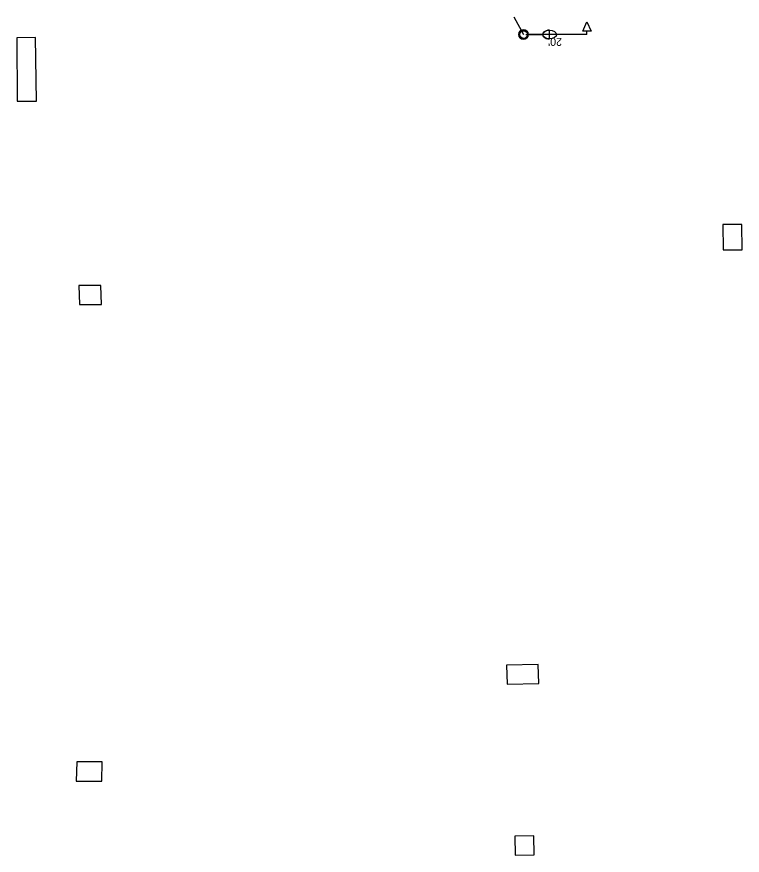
# Model space of a CAD drawing. Extents: x 596176 to 605330, y 332416 to 402398.
# Drawn here: x 601125.1 to 601353.5, y 385994.5 to 386258.5 of the extents above; entities that cross this region are included whole.
import ezdxf

# ---------------------------------------------------------------- set-up
doc = ezdxf.new("R2010")
doc.units = 0
for name, color, linetype in [('P_LTG', 7, 'Continuous'), ('P_SIG', 7, 'Continuous'), ('P_SIG_Conduit', 7, 'Continuous'), ('P_SIG_Loops', 7, 'Continuous')]:
    doc.layers.add(name, color=color, linetype=linetype)

# ---------------------------------------------------------------- blocks, each defined once
blk = doc.blocks.new('LUMINAIRES_3')
at = {"layer": 'P_LTG'}
for p, q in [((4.32, 25.12), (-4.14, 25.12)), ((0.05, 2.3), (0.05, 18.44))]:
    blk.add_line(p, q, dxfattribs=at)
blk.add_circle((0.05, 0.15), 3.68, dxfattribs=at)
blk.add_ellipse((0.09, 25.12), major_axis=(0, 6.65), ratio=0.636439, dxfattribs=at)
blk.add_ellipse((0.09, 25.12), major_axis=(0, 6.65), ratio=0.636439, start_param=1.570796, end_param=4.712389, dxfattribs=at)

msp = doc.modelspace()

# ---------------------------------------------------------------- linework, layer by layer
at = {"layer": 'P_SIG'}
for q in [(601286.14, 386252.89), (601304.64, 386253.93)]:
    msp.add_line((601304.64, 386252.88), q, dxfattribs=at)
msp.add_lwpolyline([(601303.32, 386253.93), (601304.64, 386256.88), (601305.95, 386253.93)], close=True, dxfattribs=at)
msp.add_circle((601284.64, 386252.88), 1.5, dxfattribs=at)
for start, end in [(359.9914, 179.9914), (179.9914, 359.9914)]:
    msp.add_arc((601284.64, 386252.88), 1.5, start, end, dxfattribs=at)
at = {"layer": 'P_SIG_Conduit'}
msp.add_lwpolyline([(601281.58, 386258.46), (601284.64, 386252.88)], dxfattribs=at)
at = {"layer": 'P_SIG_Loops'}
for points in [[(601125.07, 386251.85), (601125.24, 386231.85), (601131.24, 386231.9), (601131.02, 386251.9)], [(601347.46, 386193.06), (601347.54, 386185.06), (601353.54, 386185.13), (601353.46, 386193.12)], [(601144.62, 386173.89), (601144.79, 386167.89), (601151.78, 386167.89), (601151.56, 386173.89)], [(601279.3, 386054.34), (601279.47, 386048.34), (601289.48, 386048.63), (601289.3, 386054.62)], [(601144.03, 386023.89), (601143.81, 386017.89), (601151.84, 386017.89), (601152.01, 386023.89)], [(601281.92, 386000.53), (601282.02, 385994.54), (601288.02, 385994.65), (601287.91, 386000.64)]]:
    msp.add_lwpolyline(points, close=True, dxfattribs=at)

# ---------------------------------------------------------------- block references
at = {"layer": 'P_LTG', "xscale": 0.3280833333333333, "yscale": 0.3280833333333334, "rotation": -89.85001574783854}
msp.add_blockref('LUMINAIRES_3', (601284.64, 386252.88), dxfattribs=at)

# ---------------------------------------------------------------- texts
at = {"layer": 'P_SIG'}
msp.add_text("20'", height=2.52, rotation=179.9914, dxfattribs=at).set_placement((601296.79, 386251.82))

doc.saveas('drawing.dxf')
